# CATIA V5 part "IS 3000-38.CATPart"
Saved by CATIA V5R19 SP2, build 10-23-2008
Part number: IS 3000-38
Bounding box of the stored display mesh (mm): x -47.487 to 47.487, y -47.487 to 47.487, z 0 to 196
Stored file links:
  C:\Users\Bora\Desktop\3D Katı model\IS serisi\IS 3000\IS 3000-38.CATPart
  C:\Program Files\Dassault Systemes\B19\intel_a\reffiles\standard\MetricThickPitch.txt
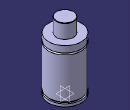
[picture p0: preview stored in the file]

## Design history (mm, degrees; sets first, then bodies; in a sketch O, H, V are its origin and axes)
Body1 (main body)
  Sketch1 on yz-plane, origin (0, 0, 0), H (0, 1, 0), V (0, 0, 1)
    point P1 (47.5, 136.5)
    point P4 (47.5, 131.5)
    point P7 (25, 195)
    point P9 (25, 195)
    point P13 (47.5, 136.5)
    point P14 (47.5, 131.5)
    line L1 (47.5, 136.5) -> (47.5, 155)
    line L2 (47.5, 13) -> (47.5, 131.5)
    line L3 (43.5, 13) -> (43.5, 8)
    arc A1 centre (24, 195) radius 1 from (25, 195) to (24, 196) ccw
    line L4 (25, 195) -> (25, 155)
    line L5 (47.5, 0) -> (47.5, 8)
    arc A2 centre (47.5, 134) radius 2.5 from (47.5, 136.5) to (47.5, 131.5) ccw
    line L6 (24, 196) -> (0, 196)
    point P15 (0, 196)
    line L7 (25, 155) -> (47.5, 155)
    line L8 (0, 0) -> (47.5, 0)
    line L9 (43.5, 8) -> (47.5, 8)
    line L10 (43.5, 13) -> (47.5, 13)
    coincidence: P15 V, P1 P13, P4 P14, P7 P9
    tangency: L6 A1
    horizontal: L7 H, L8 H, L9 H, L10 H
  Shaft1: profile Sketch1, axis Sketch1.V, angle 360
  Sketch2 on face of Shaft1 from Sketch1.L8, origin (0, 0, 0), H (1, 0, 0), V (0, -1, 0)
    point P1 (30, 0)
    distance P1 V = 30
  Hole1: placed by Sketch2, at (30, 0, 0) direction (0, 0, 1), diameter 6.647, depth 13, threaded "M8", thread diameter 8, thread depth 13, pitch 1.25
  CircPattern1: of Hole1, instances 4, angular step 90, axis from xy-plane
